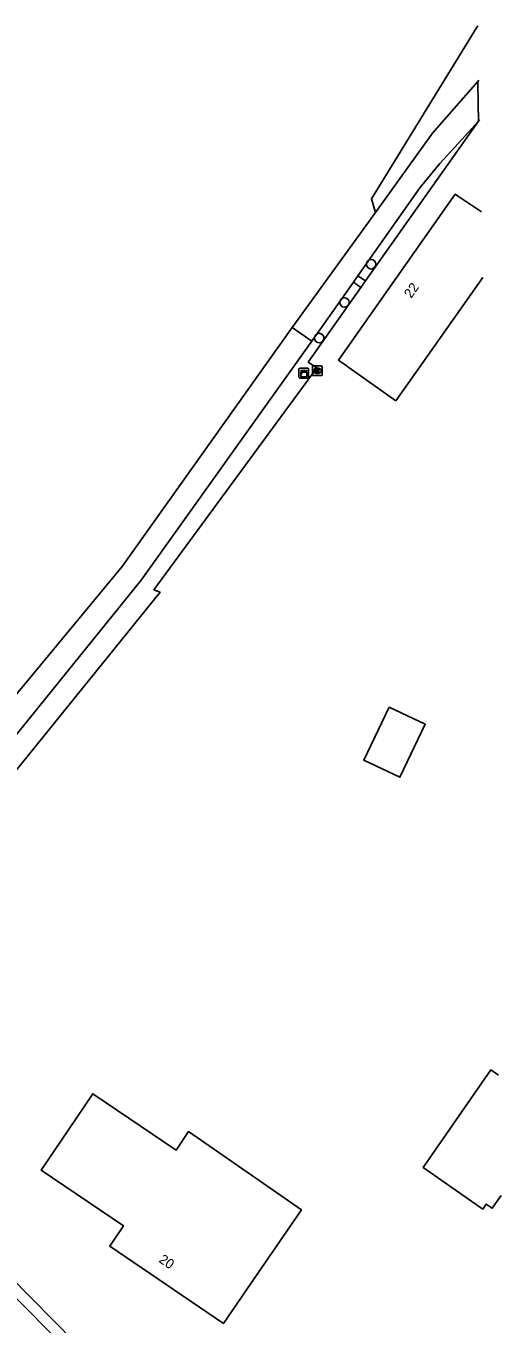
# Model space of a CAD drawing. Extents: x 163863 to 164644, y 379566 to 382155.
# Drawn here: x 164555.6 to 164604.6, y 381598.9 to 381732.6 of the extents above; entities that cross this region are included whole.
import ezdxf

# ---------------------------------------------------------------- set-up
doc = ezdxf.new("R2010")
doc.units = 0
for name, color, linetype in [('IMGEO_Berm_groen', 7, 'Continuous'), ('IMGEO_Boom', 7, 'Continuous'), ('IMGEO_Groenvoorziening', 7, 'Continuous'), ('IMGEO_Kast', 7, 'Continuous'), ('IMGEO_Pand', 7, 'Continuous'), ('IMGEO_Pand_nummerreeks', 7, 'Continuous'), ('IMGEO_Rijbaan_lokaal_halfverhard', 7, 'Continuous'), ('IMGEO_Rijbaan_lokaal_onverhard', 7, 'Continuous'), ('IMGEO_Rioolput', 7, 'Continuous'), ('IMGEO_Voetpad_open', 7, 'Continuous'), ('IMGEO_Waterloop', 7, 'Continuous')]:
    doc.layers.add(name, color=color, linetype=linetype)

msp = doc.modelspace()

# ---------------------------------------------------------------- linework, layer by layer
at = {"layer": 'IMGEO_Berm_groen'}
msp.add_lwpolyline([(164591.61, 381713.42), (164591.19, 381714.81), (164602.04, 381732.45), (164602.16, 381732.63)], dxfattribs=at)
at = {"layer": 'IMGEO_Boom'}
for centre in [(164591.16, 381708.07), (164588.41, 381704.14), (164585.82, 381700.47)]:
    msp.add_circle(centre, 0.489, dxfattribs=at)
at = {"layer": 'IMGEO_Groenvoorziening'}
for points in [[(164602.23, 381722.83), (164590.58, 381706.35)], [(164590.11, 381705.69), (164584.68, 381698), (164585.57, 381697.39), (164584.37, 381695.76), (164568.78, 381674.53), (164569.41, 381674.27), (164540.99, 381639.17), (164531.9, 381627.37), (164531.45, 381627.87)]]:
    msp.add_lwpolyline(points, dxfattribs=at)
at = {"layer": 'IMGEO_Kast'}
for p, q in [((164583.72, 381696.43), (164583.72, 381697.27)), ((164583.72, 381697.27), (164583.72, 381696.43)), ((164583.8, 381697.35), (164584.64, 381697.35)), ((164584.64, 381697.35), (164583.8, 381697.35)), ((164584.72, 381697.28), (164584.72, 381696.44)), ((164584.72, 381696.44), (164584.72, 381697.28)), ((164584.65, 381696.35), (164583.81, 381696.35)), ((164583.81, 381696.35), (164584.65, 381696.35))]:
    msp.add_line(p, q, dxfattribs=at)
for points in [[(164583.92, 381697.14), (164584.52, 381697.14), (164584.52, 381697.06), (164583.92, 381697.06), (164583.92, 381697.14)], [(164583.92, 381696.97), (164584.52, 381696.97), (164584.52, 381696.48), (164583.92, 381696.48), (164583.92, 381696.97)]]:
    msp.add_lwpolyline(points, dxfattribs=at)
msp.add_circle((164584, 381696.82), 0.0377, dxfattribs=at)
for centre, start, end in [((164583.8, 381697.27), 92.4484, 184.2845), ((164583.8, 381697.27), 92.4484, 184.2845), ((164584.64, 381697.27), 2.4484, 94.2845), ((164584.64, 381697.27), 2.4484, 94.2845), ((164583.8, 381696.43), 182.4484, 274.2845), ((164583.8, 381696.43), 182.4484, 274.2845), ((164584.64, 381696.43), 272.4484, 4.2845), ((164584.64, 381696.43), 272.4484, 4.2845)]:
    msp.add_arc(centre, 0.0779, start, end, dxfattribs=at)
at = {"layer": 'IMGEO_Pand'}
for points in [[(164593.72, 381694.01), (164587.79, 381698.2), (164599.84, 381715.28), (164600.07, 381715.13), (164602.54, 381713.47)], [(164602.68, 381706.7), (164593.72, 381694.01)], [(164593.01, 381662.45), (164596.74, 381660.67), (164594.14, 381655.22), (164590.41, 381656.99), (164593.01, 381662.45)], [(164604.56, 381612.11), (164603.65, 381610.81), (164603.04, 381611.23), (164602.69, 381610.73), (164596.53, 381615), (164603.51, 381625.08), (164604.31, 381624.53)], [(164584, 381610.64), (164578.77, 381603.04), (164575.94, 381598.92), (164564.21, 381606.9), (164565.63, 381609), (164557.14, 381614.74), (164559.95, 381618.88), (164562.46, 381622.6), (164571.05, 381616.79), (164572.34, 381618.7), (164584, 381610.64)]]:
    msp.add_lwpolyline(points, dxfattribs=at)
at = {"layer": 'IMGEO_Rijbaan_lokaal_halfverhard'}
for points in [[(164591.61, 381713.42), (164597.5, 381721.57), (164602.15, 381726.89)], [(164602.15, 381726.89), (164602.19, 381724.65), (164602.23, 381722.83)], [(164589.79, 381706.87), (164596.17, 381715.96), (164598.26, 381718.44), (164600.17, 381720.56), (164602.23, 381722.83)], [(164583.03, 381701.54), (164591.61, 381713.42)], [(164585.06, 381700.14), (164589.35, 381706.24)], [(164589.35, 381706.24), (164589.79, 381706.87)], [(164545.26, 381652.47), (164553.79, 381662.79), (164565.5, 381676.94), (164583.03, 381701.54)], [(164585.06, 381700.14), (164583.03, 381701.54)], [(164530, 381629.48), (164531.15, 381631.21), (164539.23, 381640.65), (164567.44, 381675.52), (164585.06, 381700.14)]]:
    msp.add_lwpolyline(points, dxfattribs=at)
at = {"layer": 'IMGEO_Rijbaan_lokaal_onverhard'}
for points in [[(164602.15, 381726.89), (164602.27, 381727.03)], [(164602.36, 381722.96), (164602.23, 381722.83)]]:
    msp.add_lwpolyline(points, dxfattribs=at)
at = {"layer": 'IMGEO_Rioolput'}
for p, q in [((164585.11, 381696.67), (164585.11, 381697.53)), ((164585.18, 381697.6), (164586.04, 381697.6)), ((164585.62, 381696.82), (164585.59, 381696.82)), ((164585.6, 381697.38), (164585.62, 381697.38)), ((164586.11, 381697.53), (164586.11, 381696.67)), ((164586.04, 381696.6), (164585.18, 381696.6))]:
    msp.add_line(p, q, dxfattribs=at)
for points in [[(164585.11, 381696.67), (164585.11, 381697.53)], [(164585.18, 381697.6), (164586.04, 381697.6)], [(164585.7, 381697.3), (164585.45, 381697.3), (164585.45, 381696.9)], [(164585.45, 381696.9), (164585.57, 381696.9), (164585.57, 381697.06), (164585.58, 381697.06)], [(164585.62, 381697.22), (164585.57, 381697.22), (164585.57, 381697.14)], [(164585.57, 381697.14), (164585.62, 381697.14)], [(164585.63, 381697.03), (164585.7, 381696.9), (164585.84, 381696.9), (164585.77, 381697.03)], [(164586.11, 381697.53), (164586.11, 381696.67)], [(164586.04, 381696.6), (164585.18, 381696.6)]]:
    msp.add_lwpolyline(points, dxfattribs=at)
for centre, radius, start, end in [((164585.19, 381697.52), 0.0765, 91.552, 178.448), ((164585.19, 381697.52), 0.0765, 91.552, 178.448), ((164585.19, 381696.68), 0.0765, 181.552, 268.448), ((164585.19, 381696.68), 0.0765, 181.552, 268.448), ((164585.58, 381697.01), 0.0533, 26.0293, 88.6989), ((164585.63, 381697.12), 0.0964, 77.0061, 93.1865), ((164585.61, 381697.33), 0.19, 274.7715, 282.9687), ((164585.64, 381697.18), 0.0378, 276.6634, 79.6772), ((164585.7, 381697.19), 0.109, 350.3612, 89.416), ((164585.7, 381697.19), 0.112, 277.5842, 350.9817), ((164585.68, 381696.97), 0.108, 29.5134, 73.7905), ((164586.03, 381697.52), 0.0765, 1.552, 88.448), ((164586.03, 381697.52), 0.0765, 1.552, 88.448), ((164586.03, 381696.68), 0.0765, 271.552, 358.448), ((164586.03, 381696.68), 0.0765, 271.552, 358.448)]:
    msp.add_arc(centre, radius, start, end, dxfattribs=at)
for centre, major_axis, ratio, start_param, end_param in [((164585.6, 381697.1), (-0.387, 0.002), 0.722429, 4.712389, 7.853982), ((164585.62, 381697.1), (-0.39, 0.002), 0.717154, 1.570796, 4.712389)]:
    msp.add_ellipse(centre, major_axis=major_axis, ratio=ratio, start_param=start_param, end_param=end_param, dxfattribs=at)
at = {"layer": 'IMGEO_Voetpad_open'}
for points in [[(164589.35, 381706.24), (164590.11, 381705.69)], [(164590.58, 381706.35), (164589.79, 381706.87)], [(164590.58, 381706.35), (164590.11, 381705.69)]]:
    msp.add_lwpolyline(points, dxfattribs=at)
at = {"layer": 'IMGEO_Waterloop'}
for points in [[(164530.68, 381628.73), (164529.92, 381627.46), (164530.34, 381625.94), (164566.8, 381589.23), (164566.97, 381589.37), (164567.8, 381588.54), (164568.04, 381588.78)], [(164531.45, 381627.87), (164530.94, 381627.08), (164567.56, 381589.98), (164567.41, 381589.82), (164568.26, 381588.99), (164568.04, 381588.78)]]:
    msp.add_lwpolyline(points, dxfattribs=at)

# ---------------------------------------------------------------- texts
at = {"layer": 'IMGEO_Pand_nummerreeks'}
for s, rotation, p in [('22', 54.5857, (164595.29, 381704.5)), ('20', 325.5767, (164569.2, 381605.32))]:
    msp.add_text(s, height=1, rotation=rotation, dxfattribs=at).set_placement(p)

doc.saveas('drawing.dxf')
